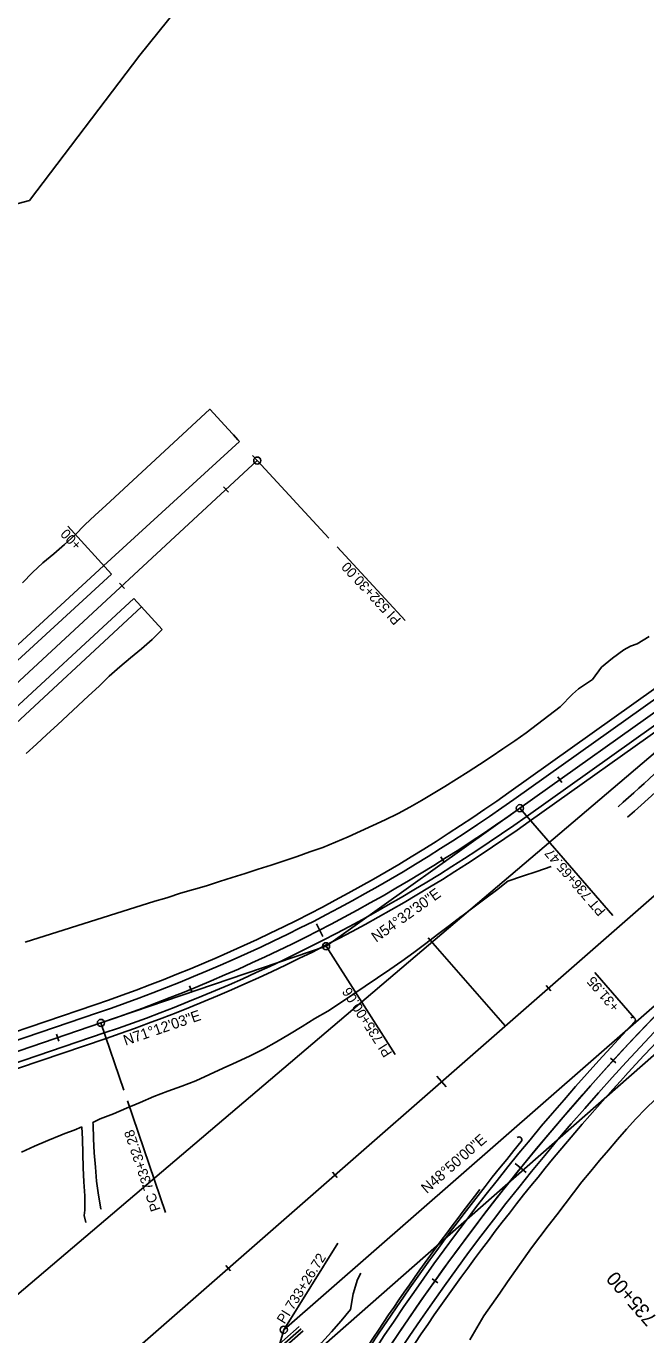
# Model space of a CAD drawing. Extents: x 1300404 to 1323571, y 237813 to 252077.
# Drawn here: x 1311522 to 1311959, y 241720 to 242643 of the extents above; entities that cross this region are included whole.
import ezdxf

# ---------------------------------------------------------------- set-up
doc = ezdxf.new("R2010")
doc.units = 0
for name, color, linetype in [('R_Const Limits', 7, 'Continuous'), ('R_Draft', 7, 'Continuous'), ('R_Flooplain', 7, 'Continuous'), ('R_Future', 7, 'Continuous'), ('R_Guardrail', 7, 'Continuous'), ('R_Horz Alg Annot', 7, 'Continuous'), ('R_Horz Alg Annot Leader', 7, 'Continuous'), ('R_Horz Alg Major Ticks', 7, 'Continuous'), ('R_Horz Alg Minor Ticks', 7, 'Continuous'), ('R_Horz Alg Station Annot', 7, 'Continuous'), ('R_Horz Alg Tangents', 7, 'Continuous'), ('R_Horz Alg Tangents Text', 7, 'Continuous'), ('R_Lane Edge', 7, 'Continuous'), ('R_Proposed', 7, 'Continuous'), ('R_Shoulder', 7, 'Continuous')]:
    doc.layers.add(name, color=color, linetype=linetype)

msp = doc.modelspace()

# ---------------------------------------------------------------- linework, layer by layer
at = {"layer": 'R_Const Limits'}
for p, q in [((1311672.58, 242350.45), (1311576.79, 242262.61)), ((1311598.05, 242239.59), (1311618.1, 242217.88))]:
    msp.add_line(p, q, dxfattribs=at)
for points in [[(1311519.54, 242250.8), (1311526.59, 242257.9), (1311533.83, 242264.8), (1311541.6, 242271.13), (1311549.21, 242277.63), (1311556.57, 242284.39), (1311563.57, 242291.56), (1311570.85, 242298.41), (1311578.26, 242305.13), (1311578.26, 242305.13), (1311578.26, 242305.13), (1311578.26, 242305.13), (1311578.26, 242305.13), (1311578.26, 242305.13), (1311578.26, 242305.13), (1311578.26, 242305.13), (1311651.65, 242373.06), (1311651.65, 242373.06), (1311664.73, 242358.92), (1311667.76, 242355.65), (1311668.31, 242355.06), (1311671.52, 242351.59), (1311672.58, 242350.45)], [(1311521.38, 241997.3), (1311612.93, 242026.24), (1311619.59, 242028.07), (1311622.07, 242028.79), (1311631.03, 242031.8), (1311640.18, 242034.42), (1311649.3, 242037.17), (1311658.38, 242040.04), (1311667.48, 242042.91), (1311676.59, 242045.83), (1311685.73, 242048.74), (1311694.91, 242051.61), (1311704.08, 242054.57), (1311713.19, 242057.71), (1311722.28, 242060.93), (1311731.39, 242064.17), (1311740.28, 242067.85), (1311749.15, 242071.61), (1311757.96, 242075.52), (1311766.72, 242079.54), (1311775.45, 242083.65), (1311784.1, 242087.92), (1311784.51, 242088.12), (1311792.64, 242092.41), (1311800.97, 242097.24), (1311809.25, 242102.15), (1311817.5, 242107.13), (1311825.68, 242112.22), (1311833.82, 242117.38), (1311841.9, 242122.64), (1311850.07, 242128.06), (1311858.4, 242133.6), (1311866.7, 242139.18), (1311874.83, 242145.01), (1311882.76, 242151.11), (1311890.71, 242157.19), (1311898.66, 242163.26), (1311907.49, 242172.2), (1311911.69, 242175.88), (1311921.68, 242182.66), (1311927.9, 242191.16), (1311935.61, 242197.58), (1311943.77, 242203.35), (1311948.32, 242205.98), (1311952.99, 242207.65), (1311961.62, 242212.77)], [(1311618.1, 242217.88), (1311611.09, 242210.78), (1311603.56, 242204.2), (1311595.73, 242197.93), (1311588.08, 242191.47), (1311580.6, 242184.83), (1311573.53, 242177.75), (1311566.14, 242171.01), (1311558.76, 242164.27), (1311551.47, 242157.42), (1311544.13, 242150.63), (1311536.79, 242143.84), (1311529.44, 242137.05), (1311522.06, 242130.31)], [(1311892.51, 242050.78), (1311882.39, 242047.19), (1311872.14, 242043.82), (1311861.94, 242040.44), (1311853.75, 242034.11), (1311845.52, 242027.8), (1311837.24, 242021.53), (1311829.31, 242015.61), (1311828.92, 242015.32), (1311820.64, 242008.99), (1311812.35, 242002.64), (1311804, 241996.36), (1311795.62, 241990.09), (1311787.1, 241984.02), (1311778.53, 241978.02), (1311769.89, 241972.09), (1311761.2, 241966.2), (1311752.48, 241960.34), (1311743.74, 241954.47), (1311734.97, 241948.6), (1311725.78, 241943.55), (1311716.83, 241937.98), (1311707.82, 241932.47), (1311698.73, 241927.09), (1311689.59, 241921.79), (1311680.11, 241917.21), (1311670.56, 241912.78), (1311667.96, 241911.59), (1311660.96, 241908.46), (1311651.4, 241904.01), (1311641.8, 241899.66), (1311631.98, 241895.83), (1311622.09, 241892.22), (1311612.23, 241888.49), (1311602.53, 241884.31), (1311592.9, 241880.27), (1311583.67, 241876.36), (1311574.36, 241872.69), (1311569.23, 241870.24)], [(1311965.99, 241886.62), (1311959.06, 241879.73), (1311952.18, 241872.8), (1311945.61, 241865.57), (1311939.24, 241858.18), (1311932.94, 241850.73), (1311926.61, 241843.3), (1311920.36, 241835.81), (1311914.16, 241828.27), (1311908.09, 241820.63), (1311902.33, 241812.74), (1311896.33, 241805.05), (1311890.41, 241797.3), (1311884.42, 241789.6), (1311878.52, 241781.84), (1311872.88, 241773.88), (1311867.31, 241765.87), (1311861.67, 241757.92), (1311856.14, 241749.89), (1311850.58, 241741.89), (1311844.96, 241733.93), (1311840, 241725.51), (1311835.13, 241717.04)], [(1311561.34, 241867.09), (1311555.89, 241864.86), (1311549.45, 241862.31), (1311546.59, 241861.17), (1311537.3, 241857.41), (1311528.04, 241853.58), (1311518.95, 241849.28)], [(1311564.17, 241799.68), (1311564.17, 241799.68), (1311563.02, 241804.62), (1311563.43, 241808.34), (1311563.44, 241818.36), (1311562.92, 241828.34), (1311562.41, 241838.33), (1311562, 241848.32), (1311561.87, 241858.33), (1311561.34, 241867.09)], [(1311569.23, 241870.24), (1311569.31, 241868.71), (1311569.66, 241858.71), (1311570.14, 241848.73), (1311571.11, 241838.76), (1311571.82, 241828.78), (1311573.15, 241818.84), (1311574.87, 241809.28), (1311574.87, 241809.28), (1311574.87, 241809.28)], [(1311701.9, 241681.46), (1311703.4, 241683.31), (1311709.85, 241691.43), (1311716.7, 241699.28), (1311723.55, 241707.1), (1311730.41, 241714.9), (1311737.4, 241722.58), (1311744.27, 241730.33), (1311750.83, 241738.25), (1311752.75, 241749.31), (1311755.88, 241759.59), (1311758.29, 241763.87)]]:
    msp.add_lwpolyline(points, dxfattribs=at)
at = {"layer": 'R_Draft'}
msp.add_line((1311805.69, 242000.38), (1311860.01, 241938.25), dxfattribs=at)
at = {"layer": 'R_Flooplain'}
for p, q in [((1311643.49, 242673.94), (1311602.23, 242622.78)), ((1311602.23, 242622.78), (1311524.54, 242520.23)), ((1311459.52, 241700.85), (1312470.12, 242559.7)), ((1311524.54, 242520.23), (1311431.38, 242495.89)), ((1312629.3, 242500.87), (1311599.52, 241597.01))]:
    msp.add_line(p, q, dxfattribs=at)
at = {"layer": 'R_Future'}
for p, q in [((1311714.76, 241726.24), (1309950.43, 240183.5)), ((1311716.07, 241724.73), (1309951.75, 240181.99)), ((1311717.39, 241723.23), (1309953.06, 240180.49))]:
    msp.add_line(p, q, dxfattribs=at)
at = {"layer": 'R_Guardrail'}
msp.add_arc((1313143.24, 240808.04), 1650.1, 142.0428, 149.19537, dxfattribs=at)
at = {"layer": 'R_Horz Alg Annot Leader'}
msp.add_line((1311951.3, 241943.81), (1311923.14, 241976.01), dxfattribs=at)
for points in [[(1311685.11, 242336.91), (1311735.71, 242282.24)], [(1311551.59, 242290.76), (1311582.2, 242256.72)], [(1311741.47, 242276.02), (1311789.41, 242224.24)], [(1311870.33, 242091.8), (1311935.95, 242016.15)], [(1311733.67, 241994.48), (1311782.38, 241918.19)], [(1311574.84, 241940.41), (1311590.95, 241893.07)], [(1311593.52, 241885.54), (1311620.39, 241806.61)], [(1311741.89, 241785.14), (1311703.85, 241724)]]:
    msp.add_lwpolyline(points, dxfattribs=at)
at = {"layer": 'R_Horz Alg Major Ticks'}
for points in [[(1311681.72, 242340.58), (1311688.51, 242333.24)], [(1311726.81, 242010.31), (1311731.38, 242001.41)], [(1311811.87, 241902.81), (1311818.46, 241895.28)], [(1311867.07, 241841.29), (1311874.84, 241835)]]:
    msp.add_lwpolyline(points, dxfattribs=at)
at = {"layer": 'R_Horz Alg Minor Ticks'}
for points in [[(1311661.4, 242318.36), (1311664.79, 242314.69)], [(1311588.01, 242250.43), (1311591.41, 242246.76)], [(1311897.01, 242113.87), (1311899.91, 242109.8)], [(1311814.61, 242057.49), (1311817.28, 242053.25)], [(1311637.32, 241966.43), (1311639.21, 241961.8)], [(1311888.8, 241966.75), (1311892.09, 241962.99)], [(1311543.48, 241932.37), (1311545.09, 241927.64)], [(1311934.37, 241915.58), (1311938.06, 241912.2)], [(1311738.24, 241835.1), (1311741.53, 241831.34)], [(1311662.96, 241769.28), (1311666.25, 241765.51)], [(1311808.41, 241760), (1311812.48, 241757.1)]]:
    msp.add_lwpolyline(points, dxfattribs=at)
at = {"layer": 'R_Horz Alg Tangents'}
for p, q in [((1311733.67, 241994.48), (1311870.33, 242091.8)), ((1311703.85, 241724), (1312065.67, 242040.38)), ((1311574.84, 241940.41), (1311733.67, 241994.48)), ((1311570.49, 241262.23), (1311703.85, 241724))]:
    msp.add_line(p, q, dxfattribs=at)
at = {"layer": 'R_Lane Edge'}
for p, q in [((1311865.98, 242097.91), (1312298.3, 242405.81)), ((1311434.79, 242121.54), (1311582.2, 242256.72)), ((1311451.09, 242103.93), (1311598.05, 242239.59)), ((1311874.68, 242085.69), (1312061.54, 242218.78)), ((1310713.17, 241655.01), (1311572.42, 241947.51)), ((1310718.01, 241640.81), (1311577.25, 241933.31))]:
    msp.add_line(p, q, dxfattribs=at)
for centre, radius, start, end in [((1310902.54, 243274.26), 1582, 311.2779, 318.84481), ((1311205.57, 243025.2), 1138.42, 288.79906, 305.45833), ((1311205.57, 243025.2), 1153.42, 288.79906, 305.45833), ((1313143.24, 240808.04), 1629.52, 131.16667, 163.89183), ((1311949.85, 241942.43), 2, 316.45181, 131.16667), ((1313143.24, 240808.04), 1644.52, 136.45181, 163.89183), ((1313143.24, 240808.04), 1644.52, 136.45181, 163.89183)]:
    msp.add_arc(centre, radius, start, end, dxfattribs=at)
at = {"layer": 'R_Proposed'}
for p, q in [((1308427.57, 238936.91), (1312793.8, 242754.77)), ((1309180.37, 239595.16), (1312398.96, 242409.52)), ((1311870.33, 242091.8), (1312302.65, 242399.71)), ((1311366.68, 242042.15), (1311685.11, 242336.91)), ((1310715.59, 241647.91), (1311574.84, 241940.41))]:
    msp.add_line(p, q, dxfattribs=at)
for centre in [(1311685.11, 242336.91), (1311870.33, 242091.8), (1311733.67, 241994.48), (1311574.84, 241940.41), (1311703.85, 241724)]:
    msp.add_circle(centre, 2.5, dxfattribs=at)
for centre, radius, start, end in [((1311205.57, 243025.2), 1145.92, 288.79906, 305.45833), ((1313143.24, 240808.04), 1637.02, 131.16667, 163.89183), ((1313143.24, 240808.04), 1637.02, 131.16667, 163.04191)]:
    msp.add_arc(centre, radius, start, end, dxfattribs=at)
at = {"layer": 'R_Shoulder'}
for p, q in [((1311862.49, 242102.8), (1312294.82, 242410.7)), ((1311429.37, 242127.43), (1311576.79, 242262.61)), ((1311456.52, 242098.06), (1311603.48, 242233.71)), ((1311877, 242082.44), (1312050.03, 242205.67)), ((1311041.55, 241773.13), (1311570.49, 241953.19)), ((1310766.63, 241653.14), (1311578.54, 241929.52))]:
    msp.add_line(p, q, dxfattribs=at)
for centre, radius, start, end in [((1310902.23, 243273.99), 1572, 311.2928, 317.03936), ((1311205.57, 243025.2), 1132.42, 288.79906, 305.45833), ((1311205.57, 243025.2), 1157.42, 288.79906, 305.45833), ((1313143.24, 240808.04), 1623.52, 131.16667, 149.50693), ((1313143.24, 240808.04), 1648.52, 140.49476, 149.50693), ((1311869.76, 241858.01), 2, 320.49476, 130.97311)]:
    msp.add_arc(centre, radius, start, end, dxfattribs=at)

# ---------------------------------------------------------------- texts
at = {"layer": 'R_Horz Alg Annot'}
for s, rotation, p in [('+00', 133.21833, (1311561.74, 242277.84)), ('PI 532+30.00', 132.78965, (1311787.02, 242225.01)), ('PT 736+65.47', 130.93961, (1311931.26, 242019.55)), ('+31.95', 130.57689, (1311941.1, 241951.99)), ('PI 735+00.06', 122.55987, (1311780.55, 241919.11)), ('PC 733+32.28', 108.79906, (1311617.01, 241808.85)), ('PI 733+26.72', 58.11412, (1311704.33, 241727.63))]:
    msp.add_text(s, height=7, rotation=rotation, dxfattribs=at).set_placement(p)
at = {"layer": 'R_Horz Alg Station Annot'}
msp.add_text('735+00', height=10, rotation=131.16667, dxfattribs=at).set_placement((1311967.67, 241732.23))
at = {"layer": 'R_Horz Alg Tangents Text'}
for s, rotation, p in [('N54%%d32\'30"E', 35.45833, (1311768.98, 241996.9)), ('N71%%d12\'03"E', 18.79906, (1311592.18, 241924.29)), ('N48%%d50\'00"E', 41.16667, (1311804.71, 241819.69))]:
    msp.add_text(s, height=7.5, rotation=rotation, dxfattribs=at).set_placement(p)

doc.saveas('drawing.dxf')
